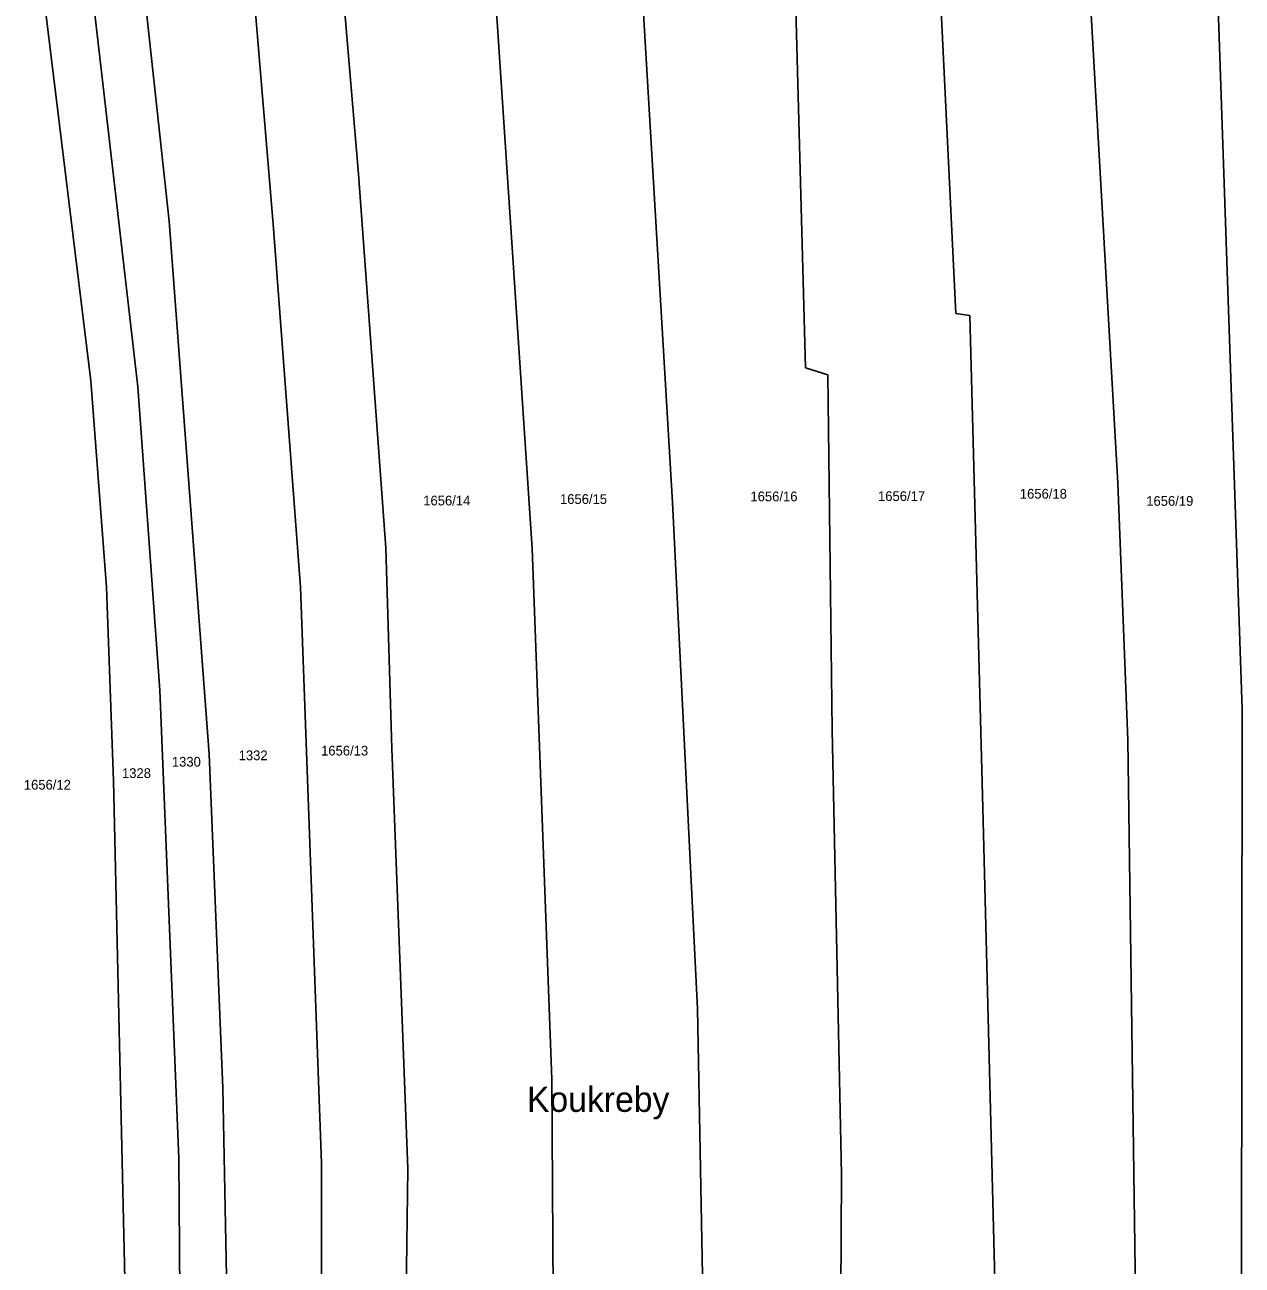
# Model space of a CAD drawing. Extents: x -763296 to -761805, y -1153670 to -1152034.
# Drawn here: x -762969 to -762756.6, y -1152752.7 to -1152536.1 of the extents above; entities that cross this region are included whole.
import ezdxf

# ---------------------------------------------------------------- set-up
doc = ezdxf.new("R2010")
doc.units = 0
for name, color, linetype in [('Vrstva 1', 7, 'Continuous'), ('Vrstva 15', 7, 'Continuous'), ('Vrstva 18', 7, 'Continuous'), ('Vrstva 6', 7, 'Continuous')]:
    doc.layers.add(name, color=color, linetype=linetype)

msp = doc.modelspace()

# ---------------------------------------------------------------- linework, layer by layer
at = {"layer": 'Vrstva 1'}
for p, q in [((-762760.81, -1152531.41), (-762756.58, -1152655.62)), ((-762756.58, -1152655.62), (-762756.75, -1152790.35))]:
    msp.add_line(p, q, dxfattribs=at)
at = {"layer": 'Vrstva 6'}
for p, q in [((-762943.84, -1152570.41), (-762960.36, -1152419.02)), ((-762806.56, -1152586.55), (-762811.9, -1152475.92)), ((-762910.79, -1152562.21), (-762917.97, -1152478.12)), ((-762835.43, -1152497.57), (-762832.79, -1152596.05)), ((-762784.94, -1152498.4), (-762778.31, -1152616.16)), ((-762925.69, -1152570.94), (-762930.82, -1152509.47)), ((-762949.29, -1152599.34), (-762958.22, -1152522.34)), ((-762880.47, -1152627.59), (-762887.48, -1152522.25)), ((-762957.5, -1152598.32), (-762966.34, -1152526.12)), ((-762856, -1152619.54), (-762861.53, -1152526.57)), ((-762906.04, -1152627.46), (-762910.79, -1152562.21)), ((-762936.85, -1152663.48), (-762943.84, -1152570.41)), ((-762920.9, -1152634.35), (-762925.69, -1152570.94)), ((-762804.11, -1152586.9), (-762806.56, -1152586.55)), ((-762801.85, -1152672.85), (-762804.11, -1152586.9)), ((-762832.79, -1152596.05), (-762828.87, -1152597.22)), ((-762954.75, -1152634.35), (-762957.5, -1152598.32)), ((-762828.87, -1152597.22), (-762828.15, -1152659.3)), ((-762945.47, -1152652.28), (-762949.29, -1152599.34)), ((-762778.31, -1152616.16), (-762776.51, -1152660.99)), ((-762851.61, -1152707.93), (-762856, -1152619.54)), ((-762904.96, -1152662.52), (-762906.04, -1152627.46)), ((-762877.08, -1152720.29), (-762880.47, -1152627.59)), ((-762953.58, -1152668.14), (-762954.75, -1152634.35)), ((-762917.24, -1152734.89), (-762920.9, -1152634.35)), ((-762942.16, -1152734.1), (-762945.47, -1152652.28)), ((-762828.15, -1152659.3), (-762826.51, -1152736.89)), ((-762776.51, -1152660.99), (-762774.75, -1152790.14)), ((-762902.21, -1152735.88), (-762904.96, -1152662.52)), ((-762934.49, -1152721.82), (-762936.85, -1152663.48)), ((-762951.17, -1152773.14), (-762953.58, -1152668.14)), ((-762798.9, -1152789.86), (-762801.85, -1152672.85)), ((-762850.61, -1152761.35), (-762851.61, -1152707.93)), ((-762932.91, -1152798.75), (-762934.49, -1152721.82)), ((-762876.51, -1152800.03), (-762877.08, -1152720.29)), ((-762941.74, -1152789.3), (-762942.16, -1152734.1)), ((-762917.2, -1152818.33), (-762917.24, -1152734.89)), ((-762902.89, -1152796.26), (-762902.21, -1152735.88)), ((-762826.51, -1152736.89), (-762826.97, -1152806.92))]:
    msp.add_line(p, q, dxfattribs=at)

# ---------------------------------------------------------------- texts
at = {"layer": 'Vrstva 15'}
msp.add_text('Koukreby', height=4.4, dxfattribs=at).set_placement((-762881.399, -1152725.94))
at = {"layer": 'Vrstva 18'}
for s, p in [('1656/16', (-762842.403, -1152619.33)), ('1656/17', (-762820.132, -1152619.28)), ('1656/18', (-762795.383, -1152618.86)), ('1656/14', (-762899.503, -1152620.05)), ('1656/15', (-762875.639, -1152619.79)), ('1656/19', (-762773.323, -1152620.12)), ('1332', (-762931.713, -1152664.54)), ('1656/13', (-762917.33, -1152663.72)), ('1330', (-762943.366, -1152665.66)), ('1328', (-762952.076, -1152667.64)), ('1656/12', (-762969.206, -1152669.67))]:
    msp.add_text(s, height=1.7, dxfattribs=at).set_placement(p)

doc.saveas('drawing.dxf')
